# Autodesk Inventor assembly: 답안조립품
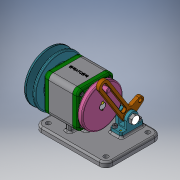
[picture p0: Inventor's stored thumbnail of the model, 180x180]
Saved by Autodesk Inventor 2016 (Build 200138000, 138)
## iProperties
Created: 2020-11
Part Number: 답안조립품
Document SubType Name: Assembly
Designer: Windows7
Mass: 1532.4 g
Surface Area: 1486.39 cm^2
Volume: 469.454 cm^3
Density: 3.26422 g/cm^3
Author: Windows7
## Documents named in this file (19)
- C:\Users\Windows7\Desktop\601106V1008\답안조립품.iam
- C:\Users\Windows7\Desktop\601106V1008\본체.ipt
- C:\Users\Windows7\Desktop\601106V1008\V-벨트풀리.ipt
- C:\Users\Windows7\Desktop\601106V1008\너트 M10x1.ipt
- C:\Users\Windows7\Desktop\601106V1008\베어링 6004.ipt
- C:\Users\Windows7\Desktop\601106V1008\오일 실 17 30 5.ipt
- C:\Users\Windows7\Desktop\601106V1008\커버.ipt
- C:\Users\Windows7\Desktop\601106V1008\볼트 M4.ipt
- C:\Users\Windows7\Desktop\601106V1008\돌림판.ipt
- C:\Users\Windows7\Desktop\601106V1008\멈춤나사 M3x5.ipt
- C:\Users\Windows7\Desktop\601106V1008\축.ipt
- C:\Users\Windows7\Desktop\601106V1008\키 4 x 4 x 8.ipt
- C:\Users\Windows7\Desktop\601106V1008\키 5 x 5 x 12.ipt
- C:\Users\Windows7\Desktop\601106V1008\너트 M8.ipt
- C:\Users\Windows7\Desktop\601106V1008\와셔 8x15.5.ipt
- C:\Users\Windows7\Desktop\601106V1008\크랭크.ipt
- C:\Users\Windows7\Desktop\601106V1008\핀 3 x 8.ipt
- C:\Users\Windows7\Desktop\601106V1008\힌지 축.ipt
- C:\Users\Windows7\Desktop\601106V1008\힌지.ipt
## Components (3 placed, 2 different names)
1. V-벨트풀리:1 — 플러쉬:4
2. 핀 3 x 8:1 — 플러쉬:6
3. 핀 3 x 8:2 — 플러쉬:5
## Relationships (3: Flush 3)
- 플러쉬:4 [Flush]: V-벨트풀리:1
- 플러쉬:5 [Flush]: 핀 3 x 8:2
- 플러쉬:6 [Flush]: 핀 3 x 8:1
